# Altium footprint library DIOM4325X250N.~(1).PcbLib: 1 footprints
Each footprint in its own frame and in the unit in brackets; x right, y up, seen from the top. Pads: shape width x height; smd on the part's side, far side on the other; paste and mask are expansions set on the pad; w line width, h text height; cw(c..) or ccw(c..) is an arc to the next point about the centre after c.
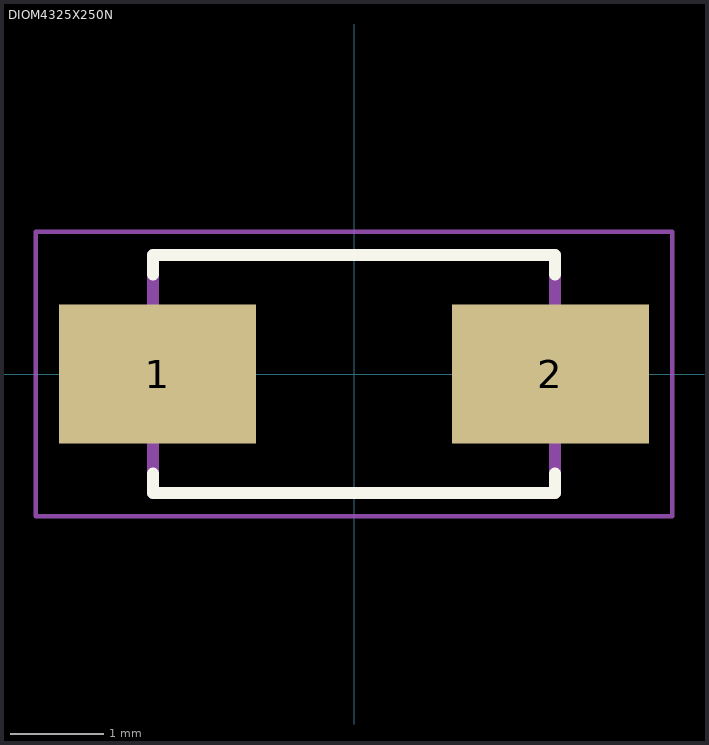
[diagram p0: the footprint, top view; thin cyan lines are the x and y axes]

## DIOM4325X250N [mm]
pads (2):
  rect 2.12x1.5 smd: 1(-2.115,0) 2(2.115,0)
Top Overlay:
  lines w0.127: -2.165,-1.07 -2.165,-1.28 2.165,-1.28 2.165,-1.07 ; -2.165,1.07 -2.165,1.28 2.165,1.28 2.165,1.07
Mechanical 13:
  lines w0.127: -2.165,-1.28 -2.165,1.28 2.165,1.28 2.165,-1.28 -2.165,-1.28
Mechanical 15:
  lines w0.05: -3.425,-1.53 -3.425,1.53 3.425,1.53 3.425,-1.53 -3.425,-1.53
